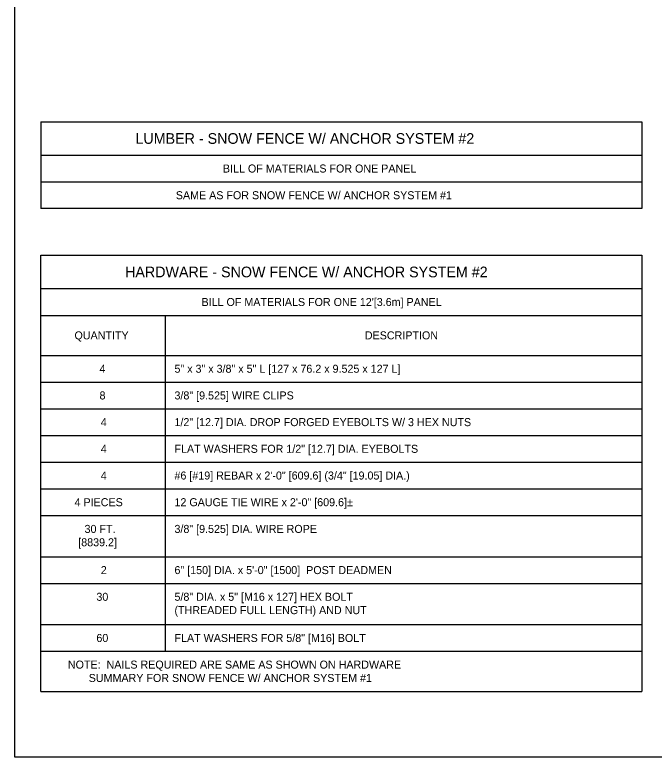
# Model space of a CAD drawing. Extents: x 49991.4 to 50021, y 49987.6 to 50011.4.
# Drawn here: x 49999.38 to 50004.17, y 49987.8 to 49993.36 of the extents above; entities that cross this region are included whole.
import ezdxf

# ---------------------------------------------------------------- set-up
doc = ezdxf.new("R2010")
doc.units = 0
doc.layers.add('Level 1', color=7, linetype='Continuous')
doc.layers.add('Level 2', color=7, linetype='Continuous')

msp = doc.modelspace()

# ---------------------------------------------------------------- linework, layer by layer
at = {"layer": 'Level 1'}
msp.add_lwpolyline([(49999.3835, 49998.9992), (50016.7501, 49998.9992), (50016.7501, 49987.7988), (49999.3835, 49987.7988)], close=True, dxfattribs=at)
at = {"layer": 'Level 2'}
for p, q in [((49999.5794, 49992.5588), (50004.0794, 49992.5588)), ((49999.5794, 49992.5588), (49999.5794, 49991.9088)), ((50004.0794, 49992.5588), (50004.0794, 49991.9088)), ((49999.5794, 49992.3088), (50004.0794, 49992.3088)), ((49999.5794, 49992.1088), (50004.0794, 49992.1088)), ((50004.0794, 49991.9088), (49999.5794, 49991.9088)), ((49999.5794, 49991.5588), (50004.0794, 49991.5588)), ((49999.5794, 49988.2918), (49999.5794, 49991.5588)), ((50004.0794, 49991.5588), (50004.0794, 49988.2918)), ((49999.5794, 49991.3088), (50004.0794, 49991.3088)), ((49999.5794, 49991.1088), (50004.0794, 49991.1088)), ((50000.5093, 49991.1088), (50000.5093, 49988.5918)), ((49999.5794, 49990.8088), (50004.0794, 49990.8088)), ((49999.5794, 49990.6088), (50004.0794, 49990.6088)), ((49999.5794, 49990.4088), (50004.0794, 49990.4088)), ((49999.5794, 49990.2088), (50004.0794, 49990.2088)), ((49999.5794, 49990.0088), (50004.0794, 49990.0088)), ((49999.5794, 49989.8088), (50004.0794, 49989.8088)), ((49999.5794, 49989.6088), (50004.0794, 49989.6088)), ((49999.5794, 49989.3003), (50004.0794, 49989.3003)), ((49999.5794, 49989.1003), (50004.0794, 49989.1003)), ((49999.5794, 49988.7918), (50004.0794, 49988.7918)), ((49999.5794, 49988.5918), (50004.0794, 49988.5918)), ((49999.5794, 49988.2918), (50004.0794, 49988.2918))]:
    msp.add_line(p, q, dxfattribs=at)

# ---------------------------------------------------------------- texts
for s, height, p in [('LUMBER - SNOW FENCE W/ ANCHOR SYSTEM #2', 0.08, (50000.2868, 49992.3938)), ('BILL OF MATERIALS FOR ONE PANEL', 0.06, (50000.9422, 49992.1788)), ('SAME AS FOR SNOW FENCE W/ ANCHOR SYSTEM #1', 0.06, (50000.5894, 49991.9788)), ('HARDWARE - SNOW FENCE W/ ANCHOR SYSTEM #2', 0.08, (50000.2091, 49991.3938)), ("BILL OF MATERIALS FOR ONE 12'[3.6m] PANEL", 0.06, (50000.7819, 49991.1788)), ('QUANTITY', 0.06, (49999.8303, 49990.9288)), ('DESCRIPTION', 0.06, (50002.0054, 49990.9288)), ('4', 0.06, (50000.0178, 49990.6788)), ('5" x 3" x 3/8" x 5" L [127 x 76.2 x 9.525 x 127 L]', 0.06, (50000.5793, 49990.6788)), ('8', 0.06, (50000.0178, 49990.4788)), ('3/8" [9.525] WIRE CLIPS', 0.06, (50000.5793, 49990.4788)), ('4', 0.06, (50000.0273, 49990.2788)), ('1/2" [12.7] DIA. DROP FORGED EYEBOLTS W/ 3 HEX NUTS', 0.06, (50000.5793, 49990.2788)), ('4', 0.06, (50000.0274, 49990.0788)), ('FLAT WASHERS FOR 1/2" [12.7] DIA. EYEBOLTS', 0.06, (50000.5793, 49990.0788)), ('4', 0.06, (50000.0274, 49989.8788)), ('#6 [#19] REBAR x 2\'-0" [609.6] (3/4" [19.05] DIA.)', 0.06, (50000.5793, 49989.8788)), ('4 PIECES', 0.06, (49999.8308, 49989.6788)), ('12 GAUGE TIE WIRE x 2\'-0" [609.6]±', 0.06, (50000.5793, 49989.6788)), ('30 FT.', 0.06, (49999.9057, 49989.4788)), ('3/8" [9.525] DIA. WIRE ROPE', 0.06, (50000.5793, 49989.4788)), ('[8839.2]', 0.06, (49999.8584, 49989.3788)), ('2', 0.06, (50000.0273, 49989.1703)), ('6" [150] DIA. x 5\'-0" [1500]  POST DEADMEN', 0.06, (50000.5793, 49989.1703)), ('5/8" DIA. x 5" [M16 x 127] HEX BOLT', 0.06, (50000.5793, 49988.9703)), ('30', 0.06, (49999.9943, 49988.9703)), ('(THREADED FULL LENGTH) AND NUT', 0.06, (50000.5793, 49988.8703)), ('60', 0.06, (49999.9943, 49988.6618)), ('FLAT WASHERS FOR 5/8" [M16] BOLT', 0.06, (50000.5793, 49988.6618)), ('NOTE:  NAILS REQUIRED ARE SAME AS SHOWN ON HARDWARE', 0.06, (49999.7807, 49988.4622)), ('       SUMMARY FOR SNOW FENCE W/ ANCHOR SYSTEM #1', 0.06, (49999.7807, 49988.3622))]:
    msp.add_text(s, height=height, dxfattribs=at).set_placement(p)

doc.saveas('drawing.dxf')
